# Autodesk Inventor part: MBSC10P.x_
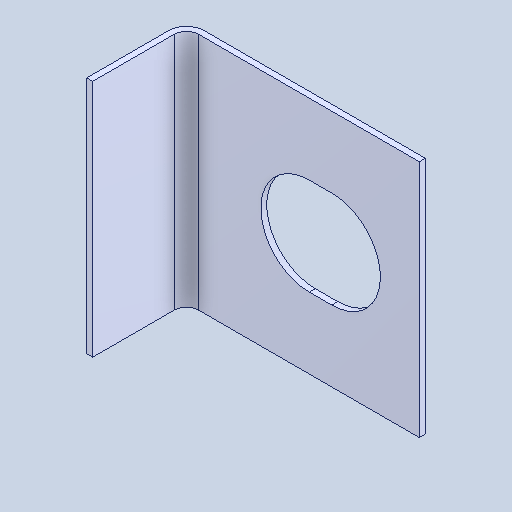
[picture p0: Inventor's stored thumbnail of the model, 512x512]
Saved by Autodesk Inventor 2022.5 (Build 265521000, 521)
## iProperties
Created: 2024-05
Part Number: MBSC10P.x_
Material: 一般
Document SubType Name: Modeling
Designer: ImaoCorp
Density: 1 g/cm^3
Appearance: 既定
Author: ImaoCorp
Sending System: SOLIDWORKS 2022-2022290
MC: AMD64
MC_MODEL: Intel64 Family 6 Model 60 Stepping 3, GenuineIntel
OS: Windows_NT
FRU: Parasolid Version 33.1, build 260,  4-25-2022
FORMAT: text
GUISE: transmit
KEY: FILEMBSC10P.x_t
DATE: Mon May 20 16:27:46 2024
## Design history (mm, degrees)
feature "Base1"
node "ソリッド1"
